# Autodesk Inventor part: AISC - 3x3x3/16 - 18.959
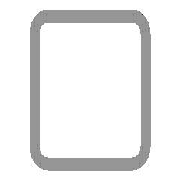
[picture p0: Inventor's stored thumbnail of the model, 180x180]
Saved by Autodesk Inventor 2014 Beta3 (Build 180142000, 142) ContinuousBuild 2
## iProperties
Created: 2011-11
Part Number: AISC - 3x3x3/16 - 18.959
Material: Steel, Mild
Description: Tube
Document SubType Name: Modeling
Standard: ANSI
Designer: Thom Tremblay
Standards Organization: ANSI
Language: en-US
Size Designation: 3x3x3/16
Categories: <MemberInstance><Categories><Category DisplayName="Structural Shapes" InternalName="089c4875-fa83-4c05-b084-43b9cc11f5ed" Mnemonic="GRDR"><CategoryParameter Dis
Stock Number: 3x3x3/16
Density: 7.86 g/cm^3
Appearance: Steel
_CCFamilyMember: 9
_CCFamilyDisplayName: ANSI AISC (Square) - Tube
_FrameMemberDoc: Frame Member File
_Version: 15.0.0
_GetPNFromCC: 1
IsCustomPart: 1
G_L: 18.959 in
G_W: 3.000 in
G_H: 3.000 in
Author: Thom Tremblay
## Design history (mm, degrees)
node "Start plane"
node "End plane"
node "Driven Length"
  sketch "Sketch3"
    geometry: L1 (0, 0)-(10, 0) reference
    constraints: 2 end point, 1 horizontal
  workplane "Work Plane3"
  sketch "Sketch4"
    geometry: L1 (-2, 0)-(12, 0) reference; L2 (-53.34, 481.559)-(53.34, 481.559) reference
    dimensions: "d19" = 481.55872 distance between parallel lines of L1 L2 (derived)
sketch "Sweep Path"
  geometry: L1 through (609.6, 0) direction (1, 0); 1 other entity
  constraints: 5 horizontal
node "Orientation Work Plane"
feature "Body" dims "d20" = 0
body "Solid1"
sketch "Sketch"
  geometry: L1 (-38.1, -28.575)-(-38.1, 28.575); L2 (-28.575, 38.1)-(28.575, 38.1); L3 (38.1, 28.575)-(38.1, -28.575); L4 (28.575, -38.1)-(-28.575, -38.1); L5 (-28.575, 33.337)-(28.575, 33.338); L6 (33.338, 28.575)-(33.338, -28.575); L7 (28.575, -33.337)-(-28.575, -33.338); L8 (-33.338, -28.575)-(-33.338, 28.575); L9 (0, 36.948)-(0, -36.948); L10 (-23.079, 0)-(23.079, 0); A1 r 9.525 centre (-28.575, -28.575) between (-38.1, -28.575) and (-28.575, -38.1); A2 r 9.525 centre (-28.575, 28.575) between (-28.575, 38.1) and (-38.1, 28.575); A3 r 9.525 centre (28.575, 28.575) between (38.1, 28.575) and (28.575, 38.1); A4 r 9.525 centre (28.575, -28.575) between (28.575, -38.1) and (38.1, -28.575); A5 r 4.763 centre (-28.575, 28.575) between (-28.575, 33.337) and (-33.338, 28.575); A6 r 4.763 centre (28.575, 28.575) between (33.338, 28.575) and (28.575, 33.338); A7 r 4.763 centre (28.575, -28.575) between (28.575, -33.337) and (33.338, -28.575); A8 r 4.763 centre (-28.575, -28.575) between (-33.338, -28.575) and (-28.575, -33.338)
  constraints: 20 end point, 16 point on circle, 8 centre point, 8 tangent, 4 parallel, 3 equal radius, 2 perpendicular, 7 other
  dimensions: "d10" = 76.2 distance between parallel lines of L2 L4 (= G_H); "d11" = 76.2 distance between parallel lines of L1 L3 (= G_W); "d12" = 4.7625 distance between parallel lines of L3 L6 (= G_T); "d15" = 38.1 distance between parallel lines of L2 L10 (= 0.5 x d10); "d16" = 38.1 distance between parallel lines of L9 L3 (= 0.5 x d11); "d17" = 9.525 radius of A1 (= G_IR)
other parameters: "G_W" = 76.2 [user parameter; used in 1 equation term], "G_H" = 76.2 [user parameter; used in 1 equation term], "G_T" = 4.7625 [user parameter; used in 1 equation term], "G_IR" = 9.525 [user parameter; used in 1 equation term], "G_L" = 481.55872 (= d19) [user parameter], "G_OFFSET_START" = 0 [user parameter; used in 1 equation term], "G_OFFSET_END" = 0 [user parameter; used in 1 equation term], "d13" = 0 (computed from G_OFFSET_START), "d14" = 481.55872 (= G_OFFSET_END + B_L), "B_L" = 481.55872 [user parameter; used in 1 equation term], "d18" = 90 deg
